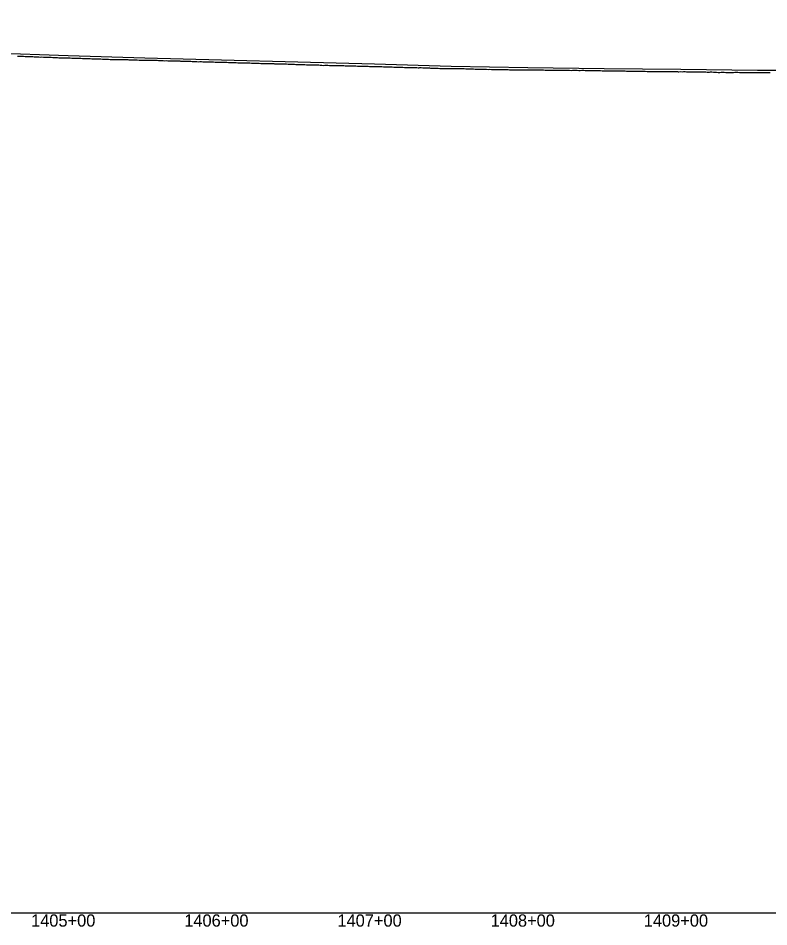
# Model space of a CAD drawing. Extents: x -3793 to 50787, y -1075 to 6138.
# Drawn here: x 27793 to 28283, y 2991 to 3584 of the extents above; entities that cross this region are included whole.
import ezdxf

# ---------------------------------------------------------------- set-up
doc = ezdxf.new("R2010")
doc.units = 0
for name, color, linetype in [('RD_DDB_Profile_EX', 7, 'Continuous'), ('RD_DDB_Profile_PR', 7, 'Continuous'), ('RD_DDB_StaTX', 7, 'Continuous'), ('RD_GPK_Profile_Cell', 7, 'Continuous')]:
    doc.layers.add(name, color=color, linetype=linetype)

msp = doc.modelspace()

# ---------------------------------------------------------------- linework, layer by layer
at = {"layer": 'RD_DDB_Profile_EX'}
for points in [[(27792.802006, 3558.86656), (27793.801525, 3558.821955), (27794.802152, 3558.775915), (27795.801666, 3558.72707), (27796.801183, 3558.71953), (27797.802846, 3558.69307), (27798.793272, 3558.602325), (27799.794919, 3558.582105), (27800.794428, 3558.57435), (27801.796074, 3558.51936), (27802.79538, 3558.516025), (27803.796181, 3558.47408), (27804.795683, 3558.4293), (27805.797319, 3558.42407), (27806.796608, 3558.329295), (27807.798243, 3558.243605), (27808.797737, 3558.307295), (27809.863771, 3558.26974), (27810.863378, 3558.174945), (27811.246199, 3558.136975), (27811.862929, 3558.084455), (27812.864008, 3558.129125), (27813.863524, 3558.121015), (27814.864604, 3558.070125), (27815.86412, 3557.97951), (27816.865201, 3557.932925), (27818.015661, 3557.92575), (27818.865873, 3557.877955), (27819.865301, 3557.828405), (27820.779903, 3557.82721), (27821.260838, 3557.749885), (27822.261024, 3557.704515), (27823.26929, 3557.750635), (27824.268623, 3557.705275), (27824.785123, 3557.70541), (27825.355783, 3557.758235), (27826.267229, 3557.667225), (27827.264619, 3557.623375), (27828.263912, 3557.5825), (27829.263205, 3557.487195), (27830.262498, 3557.47851), (27831.554585, 3557.437875), (27832.270152, 3557.438005), (27833.269406, 3557.43355), (27834.268659, 3557.429095), (27835.266009, 3557.330675), (27836.265263, 3557.29425), (27837.264516, 3557.24879), (27838.324046, 3557.294295), (27839.262988, 3557.28508), (27840.263087, 3557.239435), (27841.271205, 3557.13964)], [(27841.271205, 3557.13964), (27842.270421, 3557.093955), (27843.269637, 3557.093755), (27844.266953, 3557.045225), (27845.266352, 3556.99935), (27846.265532, 3557.039875), (27847.264711, 3556.99397), (27848.263891, 3556.943545), (27849.26307, 3556.93863), (27850.322104, 3556.89285), (27851.33005, 3556.79749), (27851.86297, 3556.77155), (27852.237431, 3556.753235), (27853.326473, 3556.707175), (27854.235713, 3556.70654), (27855.325118, 3556.74257), (27856.234865, 3556.74198), (27857.322872, 3556.72808), (27858.233147, 3556.727525), (27858.632432, 3556.687325), (27859.321434, 3556.631335), (27860.23898, 3556.63257), (27860.928586, 3556.631885), (27861.936616, 3556.59029), (27862.935546, 3556.58517), (27863.93275, 3556.581535), (27864.932544, 3556.539715), (27865.401893, 3556.492325), (27865.93164, 3556.42994), (27866.930538, 3556.429045), (27867.927711, 3556.429605), (27868.935538, 3556.383465), (27869.935474, 3556.38243), (27870.932464, 3556.33752), (27872.171355, 3556.297195), (27872.930425, 3556.29221), (27873.929477, 3556.27542), (27874.927277, 3556.27596), (27875.935093, 3556.229505), (27876.934147, 3556.223965), (27877.931106, 3556.17021), (27878.940817, 3556.169495), (27879.929831, 3556.221905), (27880.928851, 3556.17042), (27881.925783, 3556.116545), (27882.933776, 3556.11134), (27883.932631, 3556.11417), (27884.930538, 3556.06434), (27885.929381, 3556.01299), (27886.928376, 3556.015365), (27887.927203, 3555.963805), (27888.979187, 3555.868315), (27889.977587, 3555.90878), (27890.976767, 3555.86122), (27891.868992, 3555.815875), (27892.47974, 3555.785855), (27892.875019, 3555.76626), (27893.871138, 3555.763975), (27894.877096, 3555.81422), (27895.873928, 3555.764075), (27896.871553, 3555.75997), (27897.876126, 3555.669895), (27898.873639, 3555.665885), (27899.249202, 3555.646995), (27899.87041, 3555.61561), (27900.876264, 3555.565635), (27901.872424, 3555.52509), (27902.878149, 3555.52527), (27903.874885, 3555.52083), (27904.871052, 3555.46807), (27906.018664, 3555.45684), (27906.87355, 3555.421645), (27907.870878, 3555.37532), (27908.875247, 3555.31861), (27909.872702, 3555.27627), (27910.878449, 3555.230165), (27911.873711, 3555.27306), (27912.871037, 3555.26442), (27913.876688, 3555.222225), (27914.873237, 3555.17142), (27915.878323, 3555.17271), (27916.874749, 3555.12615), (27917.872107, 3555.07536), (27918.877764, 3555.070865), (27919.872904, 3555.02575), (27920.870167, 3555.024735), (27921.875613, 3554.978285), (27922.870689, 3554.924895), (27923.877063, 3554.92428), (27924.873521, 3554.87323), (27925.870653, 3554.872365), (27926.327049, 3554.87293), (27926.855678, 3554.869375), (27927.852187, 3554.86813), (27928.573679, 3554.82332), (27929.569889, 3554.822195), (27930.574702, 3554.769185), (27931.569586, 3554.71976), (27932.565391, 3554.674275), (27933.096511, 3554.67383), (27933.570679, 3554.669405)], [(27933.570679, 3554.669405), (27934.56627, 3554.62384), (27935.570183, 3554.578655), (27936.567213, 3554.57313), (27937.57113, 3554.56984), (27938.566723, 3554.52023), (27939.865973, 3554.459775), (27940.567483, 3554.42357), (27941.571419, 3554.4199), (27942.566917, 3554.42007), (27943.570734, 3554.41653), (27944.567553, 3554.36506), (27945.571375, 3554.32364), (27946.635434, 3554.27774), (27947.570718, 3554.273985), (27948.567441, 3554.272215), (27949.571173, 3554.17653), (27950.56657, 3554.172465), (27951.570417, 3554.12262), (27952.567134, 3554.11688), (27953.570857, 3554.07112), (27954.566155, 3554.06687), (27955.569915, 3554.062825), (27956.566533, 3554.06092), (27957.570188, 3554.01492), (27958.565476, 3553.96857), (27959.569132, 3554.010805), (27960.174358, 3553.948775), (27960.565818, 3553.908675), (27961.569394, 3553.90853), (27962.564578, 3553.861905), (27963.568157, 3553.85791), (27964.564664, 3553.809585), (27965.568364, 3553.7593), (27966.520069, 3553.70887), (27966.94382, 3553.708825), (27967.52428, 3553.708765), (27968.499624, 3553.70899), (27969.503077, 3553.7012), (27970.5055, 3553.652625), (27971.499007, 3553.653555), (27972.503201, 3553.5572), (27973.713281, 3553.501865), (27974.500127, 3553.465455), (27975.502526, 3553.46288), (27976.506077, 3553.458425), (27977.499415, 3553.4593), (27978.501814, 3553.41446), (27979.505357, 3553.36777), (27980.498703, 3553.318685), (27981.502833, 3553.26803), (27982.50458, 3553.264995), (27983.497902, 3553.20384), (27984.502181, 3553.20704), (27985.503775, 3553.20801), (27986.498861, 3553.15705), (27987.501373, 3553.15786), (27988.503714, 3553.15468), (27989.497996, 3553.107445), (27990.500487, 3553.012045), (27991.504588, 3552.96514), (27992.506304, 3552.823685), (27993.499601, 3552.86625), (27994.021667, 3552.89172), (27994.503689, 3552.911345), (27995.505379, 3552.869655), (27996.50041, 3552.81817), (27997.502873, 3552.81472), (27998.506183, 3552.81361), (27999.499443, 3552.813845), (28000.791128, 3552.83125), (28001.505202, 3552.766915), (28002.668502, 3552.71675), (28003.670917, 3552.667), (28004.673172, 3552.709605), (28005.752971, 3552.70594), (28006.709854, 3552.61582), (28007.703095, 3552.61186), (28008.704599, 3552.561985), (28009.706748, 3552.562285), (28010.709031, 3552.516405), (28011.711315, 3552.47053), (28012.702964, 3552.47205), (28013.704458, 3552.418175), (28014.706723, 3552.37226), (28015.708821, 3552.37235), (28016.711055, 3552.322285), (28017.704214, 3552.321855), (28018.704102, 3552.27752), (28019.706337, 3552.27342), (28020.708571, 3552.27336), (28021.099514, 3552.273335), (28021.710639, 3552.26525), (28022.703755, 3552.16864), (28023.705941, 3552.168355), (28024.705779, 3552.123765), (28025.707966, 3552.12348), (28026.710016, 3552.07334), (28027.868975, 3552.02665), (28028.705278, 3552.022205), (28029.706629, 3552.021655)], [(28029.706629, 3552.021655), (28030.708769, 3552.01318), (28031.709352, 3551.964335), (28032.457073, 3551.968475), (28033.459147, 3551.925965), (28034.638437, 3551.87305), (28035.461104, 3551.86442), (28036.461764, 3551.815355), (28037.463767, 3551.77268), (28038.464311, 3551.681895), (28039.465517, 3551.631085), (28040.457064, 3551.673655), (28041.459063, 3551.626925), (28042.459654, 3551.58173), (28043.461467, 3551.580875), (28044.461257, 3551.577595), (28045.421143, 3551.53254), (28046.423303, 3551.527495), (28047.423562, 3551.48247), (28048.416536, 3551.47716), (28049.416781, 3551.47381), (28050.418767, 3551.472765), (28051.419011, 3551.423445), (28052.420998, 3551.37641), (28053.421394, 3551.32695), (28054.423382, 3551.27588), (28054.946822, 3551.30241), (28055.423618, 3551.322455), (28056.425591, 3551.3672), (28057.416781, 3551.27128), (28058.418751, 3551.220005), (28059.41898, 3551.220455), (28060.4211, 3551.172965), (28061.716284, 3551.1287), (28062.422523, 3551.02583), (28063.422736, 3550.97998), (28064.488018, 3551.0271), (28065.488223, 3551.023395), (28066.488428, 3550.973625), (28067.488788, 3550.927655), (28068.488994, 3550.87394), (28069.568272, 3550.87394), (28070.487589, 3550.8297), (28071.487789, 3550.86772), (28072.487989, 3550.8297), (28073.488189, 3550.783695), (28074.488546, 3550.783535), (28075.488745, 3550.8255), (28076.568615, 3550.729235), (28077.487336, 3550.7768), (28078.487531, 3550.822555), (28079.486941, 3550.7723), (28080.487137, 3550.722075), (28081.487491, 3550.717705), (28082.024669, 3550.690735), (28082.487686, 3550.675355), (28083.567376, 3550.67088), (28084.513142, 3550.66828), (28085.513265, 3550.571835), (28086.513255, 3550.52951), (28087.513245, 3550.575215), (28088.794131, 3550.552785), (28089.513335, 3550.516355), (28090.513291, 3550.469785), (28091.513248, 3550.42319), (28092.512443, 3550.37841), (28093.512398, 3550.423905), (28094.512485, 3550.423205), (28095.563593, 3550.322625), (28096.512365, 3550.321895), (28097.512288, 3550.275005), (28098.069444, 3550.271325), (28099.068822, 3550.272355), (28100.067426, 3550.223355), (28101.066029, 3550.27039), (28102.333055, 3550.21046), (28103.064417, 3550.174255), (28104.07209, 3550.125375), (28105.071758, 3550.074365), (28106.070273, 3550.12115), (28107.069683, 3550.16379), (28108.068201, 3550.11852), (28109.102516, 3550.069835), (28110.066302, 3550.02608), (28111.064737, 3550.026615), (28112.063272, 3550.01895), (28113.072002, 3550.0221), (28114.071233, 3549.980685), (28115.069668, 3549.977205), (28116.069332, 3549.975765), (28117.067685, 3549.972065), (28118.066038, 3549.88038), (28119.064391, 3549.926675), (28120.050921, 3549.9212), (28121.058377, 3549.921835), (28122.056594, 3549.922285), (28122.64144, 3549.892105), (28123.056185, 3549.87869), (28124.05524, 3549.916875), (28125.053397, 3549.91709), (28126.051664, 3549.829095)], [(28126.051664, 3549.829095), (28127.051214, 3549.86946), (28128.050155, 3549.865765), (28129.057555, 3549.86221), (28129.410902, 3549.86223), (28130.055783, 3549.86609), (28131.055275, 3549.864225), (28132.233, 3549.863675), (28133.229783, 3549.869165), (28134.228003, 3549.86901), (28135.233761, 3549.87109), (28136.232766, 3549.82095), (28137.229513, 3549.77632), (28138.227693, 3549.77992), (28139.233401, 3549.777815), (28140.231583, 3549.77339), (28141.229129, 3549.728845), (28142.227183, 3549.770485), (28143.234434, 3549.72443), (28144.23114, 3549.72556), (28145.230089, 3549.724975), (28146.235746, 3549.6807), (28147.23389, 3549.680075), (28148.230598, 3549.67711), (28149.229425, 3549.67668), (28149.719287, 3549.677485), (28150.235185, 3549.678025), (28151.233293, 3549.677185), (28152.229966, 3549.67808), (28153.227944, 3549.619145), (28154.2345, 3549.5745), (28155.232606, 3549.62368), (28156.488749, 3549.627405), (28157.227232, 3549.623725), (28158.235185, 3549.618915), (28159.231824, 3549.57369), (28160.229766, 3549.576915), (28161.241489, 3549.581775), (28162.462859, 3549.577475), (28163.460822, 3549.57241), (28164.458226, 3549.52699), (28165.465359, 3549.480115), (28166.461818, 3549.48073), (28167.458411, 3549.477065), (28168.466223, 3549.472185), (28169.462815, 3549.47262), (28170.027672, 3549.443605), (28170.460876, 3549.42126), (28171.458116, 3549.379825), (28172.465227, 3549.3786), (28173.461661, 3549.374915), (28174.459707, 3549.327425), (28175.466012, 3549.28222), (28176.462577, 3549.278395), (28176.797134, 3549.277875), (28177.460605, 3549.268655), (28178.457014, 3549.222815), (28179.464906, 3549.229395), (28180.461315, 3549.229545), (28181.459335, 3549.22377), (28182.464833, 3549.22029), (28183.566596, 3549.223755), (28184.460149, 3549.26445), (28185.456534, 3549.218285), (28186.463636, 3549.21276), (28187.460786, 3549.21271), (28188.458781, 3549.16461), (28189.464405, 3549.160875), (28190.386801, 3549.112875), (28191.149975, 3549.09599), (28192.006915, 3549.095755), (28192.861584, 3549.094055), (28193.729821, 3549.00781), (28194.589316, 3549.04916), (28195.450585, 3549.00568), (28196.320573, 3549.00571), (28197.32814, 3548.960325), (28198.186723, 3548.961535), (28199.050768, 3548.96305), (28199.91379, 3548.962575), (28200.664172, 3548.95018), (28201.668507, 3549.001775), (28202.664434, 3549.006685), (28203.874981, 3548.906885), (28204.665556, 3548.90779), (28205.669873, 3548.859055), (28206.666659, 3548.812255), (28207.67089, 3548.8137), (28208.667762, 3548.85918), (28209.662788, 3548.8141), (28210.667009, 3548.861685), (28211.663808, 3548.86458), (28212.667949, 3548.86194), (28213.663662, 3548.766725), (28214.668889, 3548.766055), (28215.664604, 3548.770865), (28216.668733, 3548.77602), (28217.665525, 3548.821075), (28218.669575, 3548.814265), (28219.66522, 3548.76495), (28220.670358, 3548.814075)], [(28220.670358, 3548.814075), (28221.666002, 3548.818685), (28222.670045, 3548.72362), (28223.666784, 3548.71849), (28224.183366, 3548.693305), (28224.67079, 3548.673305), (28225.666449, 3548.715755), (28226.671419, 3548.70695), (28227.666989, 3548.757395), (28228.671039, 3548.711915), (28229.667615, 3548.614635), (28230.952828, 3548.6291), (28231.668186, 3548.659945), (28232.67208, 3548.664365), (28233.667571, 3548.618535), (28234.14484, 3548.66446), (28235.148725, 3548.614835), (28236.144157, 3548.519015), (28237.149345, 3548.56781), (28237.722289, 3548.56794), (28238.144885, 3548.56782), (28239.14863, 3548.522035), (28240.144039, 3548.564245), (28241.147904, 3548.518315), (28242.144862, 3548.51448), (28243.148487, 3548.46492), (28244.145186, 3548.467285), (28244.491751, 3548.48465), (28245.148923, 3548.51355), (28246.144188, 3548.505715), (28247.148688, 3548.367495), (28248.143184, 3548.371315), (28249.147683, 3548.37142), (28250.142949, 3548.22916), (28251.261213, 3548.192575), (28252.143331, 3548.273255), (28253.14781, 3548.31543), (28254.142288, 3548.27281), (28255.146767, 3548.261165), (28256.150371, 3548.084185), (28257.145724, 3548.08754), (28258.151496, 3548.26281), (28259.146074, 3548.25836), (28260.15042, 3548.258155), (28261.14574, 3548.303765), (28262.149345, 3548.35354), (28263.144548, 3548.306785), (28264.149008, 3548.21389), (28265.144879, 3548.211445), (28266.231661, 3548.213595), (28267.235278, 3548.25941), (28268.313209, 3548.15696), (28269.231983, 3548.111625), (28270.310863, 3548.211115), (28271.238568, 3548.212345), (28271.569598, 3548.19601), (28272.307766, 3548.163135), (28273.234526, 3548.117965), (28274.314453, 3548.11719), (28275.231973, 3548.117925), (28276.234949, 3548.11506), (28277.23929, 3548.160565), (28278.33906, 3548.16218), (28279.235246, 3548.073625), (28280.238219, 3548.07438), (28281.309873, 3548.06548), (28282.235534, 3548.06628), (28283.238508, 3548.117), (28284.232974, 3548.16193)]]:
    msp.add_lwpolyline(points, dxfattribs=at)
at = {"layer": 'RD_DDB_Profile_PR'}
for points in [[(27325.9, 3583.6015), (27375.9, 3580.5185), (27425.9, 3577.484), (27475.9, 3574.8945), (27525.9, 3572.0605), (27575.9, 3569.226), (27625.9, 3566.97), (27675.9, 3564.6165), (27725.9, 3562.9615), (27775.9, 3561.059), (27825.9, 3559.3045), (27875.9, 3557.8315), (27925.9, 3556.4725), (27975.9, 3555.061), (28025.9, 3553.7145)], [(28025.9, 3553.7145), (28075.9, 3552.3895), (28125.9, 3551.443), (28175.9, 3550.8805), (28225.9, 3550.314), (28275.9, 3549.716), (28325.9, 3549.7055)]]:
    msp.add_lwpolyline(points, dxfattribs=at)
at = {"layer": 'RD_GPK_Profile_Cell'}
msp.add_line((1000, 3000), (46549.603806, 3000), dxfattribs=at)

# ---------------------------------------------------------------- texts
at = {"layer": 'RD_DDB_StaTX'}
for s, p in [('1405+00', (27801.687695, 2991)), ('1405+00', (27801.695471, 2991)), ('1406+00', (27901.687695, 2991)), ('1406+00', (27901.695471, 2991)), ('1407+00', (28001.687695, 2991)), ('1407+00', (28001.695471, 2991)), ('1408+00', (28101.687695, 2991)), ('1408+00', (28101.695471, 2991)), ('1409+00', (28201.687695, 2991)), ('1409+00', (28201.695471, 2991))]:
    msp.add_text(s, height=8, dxfattribs=at).set_placement(p)

doc.saveas('drawing.dxf')
